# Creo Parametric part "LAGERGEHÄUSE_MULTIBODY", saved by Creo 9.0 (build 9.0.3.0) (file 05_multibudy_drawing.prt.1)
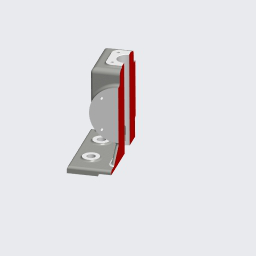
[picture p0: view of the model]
Materials in the file: STAHL

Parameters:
  SCHRAUBEN_GROESSE = "M4x.7"
  METRISCH = "JA"
  WERKSTOFF = "Stahl"
  ERSTELLER = "ARINDA"
  BENENNUNG = "XXX"
  TEILETYP = "K"
  PTC_MASTER_MATERIAL = "STAHL"

Other parameters: STEIGUNG, BOHR_DURCHM, GEWINDEDURCHMESSER, GEWINDEGÄNGE_PRO_INCH, BOHRER_SPITZENWINKEL, BOHR_TIEFE, GEWINDETIEFE, GEWINDELÄNGE, MASSE

Created from: LAGERGEHÄUSE.PRT

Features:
  1. coordinate system
  2. datum plane "RECHTS_Y-Z"
  3. datum plane "OBEN_X-Z"
  4. datum plane "VORNE_X-Y"
  5. datum axis
  6. datum axis
  7. datum axis
  8. datum point "PNT0"
  9. protrusion
  10. protrusion
  11. datum plane "DTM1"
  12. protrusion
  13. protrusion
  14. protrusion
  15. protrusion
  16. protrusion
  17. round
  18. round
  19. cut
  20. hole
  21. curve
  22. pattern
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
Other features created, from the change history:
  chamfer "Fase 1"
  patch "Verbundvolumen 1"
  datum point "Bezugspunkt ID 6860"
  datum plane "DTM2"
  datum plane "DTM3"
  planar section "D"
  planar section "E"
  extruded cut "Profil 3"
  feature "Körper Subtrahieren 1"

Other named items: RUNDER_FLANSCH, INNENKONTUR, LAGERSITZ, ECKIGER_FLANSCH, BOHRUNG_OBEN, MUSTER_OBEN, FLANSCH_OBEN, FLANSCH_LINKS, FLANSCH_RE, RIPPE_QUER, FUSS, RIPPE_LÄNGS, MUSTER-FUSSBOHRUNG, AUFDICKUNG_FUß, BOHRUNG_FUß, R6_INNEN, R3, B-B, D-D, E-E, A_X, A_Y, A_Z, CS0

Layers: 01_ACHSEN, 01_ACHSEN_STD, 01_EBENEN, 01_EBENEN_STD, 01_KOORDSYS_STD, 01_KURVEN, 01_PUNKTE, 01_PUNKTE_STD, GEWINDE, SAMMELFLÄCHEN, VOLUMENGEOMETRIE

Notes: M4x.7 | GEWINDEBOHREN | 7.000 |  BOHREN (  | 3.300 | 8.000 |   -(  |  ) BOHRUNG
